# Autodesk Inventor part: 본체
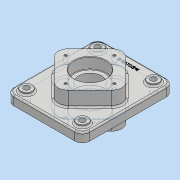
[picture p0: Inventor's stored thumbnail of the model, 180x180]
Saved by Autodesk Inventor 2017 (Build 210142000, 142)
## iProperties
Part Number: 본체
Material: 일반
Document SubType Name: Modeling
Designer: MRC
Density: 1 g/cm^3
Appearance: 기본값
Mass: 807.977 g
Surface Area: 961.758 cm^2
Volume: 807.977 cm^3
Author: MRC
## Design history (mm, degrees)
sketch "스케치1"
  geometry: L1 (-75, 90)-(75, 90); L2 (75, 90)-(75, -90); L3 (75, -90)-(-75, -90); L4 (-75, -90)-(-75, 90); L5 (-75, 90)-(75, -90); L6 (75, 90)-(-75, -90); 1 further point
  constraints: 12 end point, 2 midpoint, 2 parallel, 1 horizontal, 1 perpendicular
  dimensions: "d0" = 150 distance of L2.end L3.end; "d1" = 180 distance of L1.end L2.end
extrude "돌출1" new body sketch "스케치1" stored distance "d2" = 18; taper "d3" = 0 deg
sketch "스케치2"
  geometry: L1 (0, 70.711)-(70.711, 0); L2 (70.711, 0)-(0, -70.711); L3 (0, -70.711)-(-70.711, 0); L4 (-70.711, 0)-(0, 70.711); 2 further points
  constraints: 8 end point, 1 coincident, 1 horizontal alignment, 1 vertical alignment, 9 other
  dimensions: "d4" = 100 distance of L1.start L1.end
extrude "돌출2" join sketch "스케치2" distance "d5" = 29; taper "d7" = 0 deg; dims "d6" = 41, "d8" = 0
sketch "스케치3"
  geometry: 2 further points
  constraints: 1 coincident
hole "구멍1" sketch "스케치3" at (0, 0) diameter "d9" = 45; stored, may be unused: countersink angle "d13" = 90 deg, drill point angle "d15" = 118 deg; dims "d10" = 6, "d11" = 62, "d12" = 22, "d14" = 8
sketch "스케치4"
  geometry: C1 r 31 at (0, 0); 1 further point
  constraints: 1 centre point, 1 coincident
  dimensions: "d16" = 62 diameter of C1
extrude "돌출3" cut sketch "스케치4" distance "d17" = 22; taper "d18" = 0 deg
fillet "모깎기1" dims "d19" = 20
sketch "스케치5"
  geometry: 2 further points
  constraints: 1 vertical alignment
  dimensions: "d21" = 48 distance of point (0, 0) point (0, 48)
hole "구멍2" sketch "스케치5" at (0, 48) diameter "d22" = 4.917; stored, may be unused: countersink angle "d26" = 90 deg, drill point angle "d28" = 118 deg; dims "d23" = 10, "d24" = 62, "d25" = 22, "d27" = 13
sketch "스케치6"
  geometry: 2 further points
  constraints: 1 vertical alignment
  dimensions: "d32" = 48 distance of point (0, 0) point (0, 48)
hole "구멍3" sketch "스케치6" at (0, 48) diameter "d33" = 4.917; stored, may be unused: countersink angle "d37" = 90 deg, drill point angle "d39" = 118 deg; dims "d34" = 10, "d35" = 62, "d36" = 22, "d38" = 13
fillet "모깎기2" dims "d43" = 15
fillet "모깎기3" dims "d44" = 3
fillet "모깎기4" dims "d45" = 1
fillet "모깎기5" dims "d46" = 1
chamfer "모따기1" distance "d47" = 1; stored, may be unused: second distance "d48" = 2, angle "d49" = 45 deg
chamfer "모따기2" distance "d50" = 1; stored, may be unused: second distance "d51" = 2, angle "d52" = 45 deg
sketch "스케치9"
  geometry: L1 (-75, 75)-(-75, -75) reference; L2 (60, 90)-(-60, 90) reference; C1 r 11 at (-55, 70); 1 further point
  constraints: 1 centre point
  dimensions: "d57" = 22 diameter of C1; "d63" = 20 distance from line of C1.centre L1; "d65" = 20 distance from line of L2 C1.centre
extrude "돌출4" join sketch "스케치9" distance "d66" = 5; taper "d67" = 0 deg
sketch "스케치10"
  geometry: C1 r 5.5 at (0, 0); 1 further point
  constraints: 1 centre point
  dimensions: "d68" = 11 diameter of C1
extrude "돌출5" cut sketch "스케치10" stored distance "d69" = 5; taper "d70" = 0 deg
fillet "모깎기6" dims "d71" = 3
sketch "스케치12"
  geometry: L1 (60, 90)-(-60, 90) reference; 2 further points
  constraints: 1 vertical alignment, 1 other
  dimensions: "d72" = 15 distance from line of L1 point (0, 75)
feature "엠보싱1" sketch "스케치12" dims "d0" = 150, "d1" = 180, "d73" = 0.5, "d74" = 0
node "솔리드1"
pattern_circular "원형 패턴1" dims angle "d30" = 360 deg
pattern_circular "원형 패턴2" dims angle "d41" = 360 deg
mirror "미러1"
mirror "미러2"
